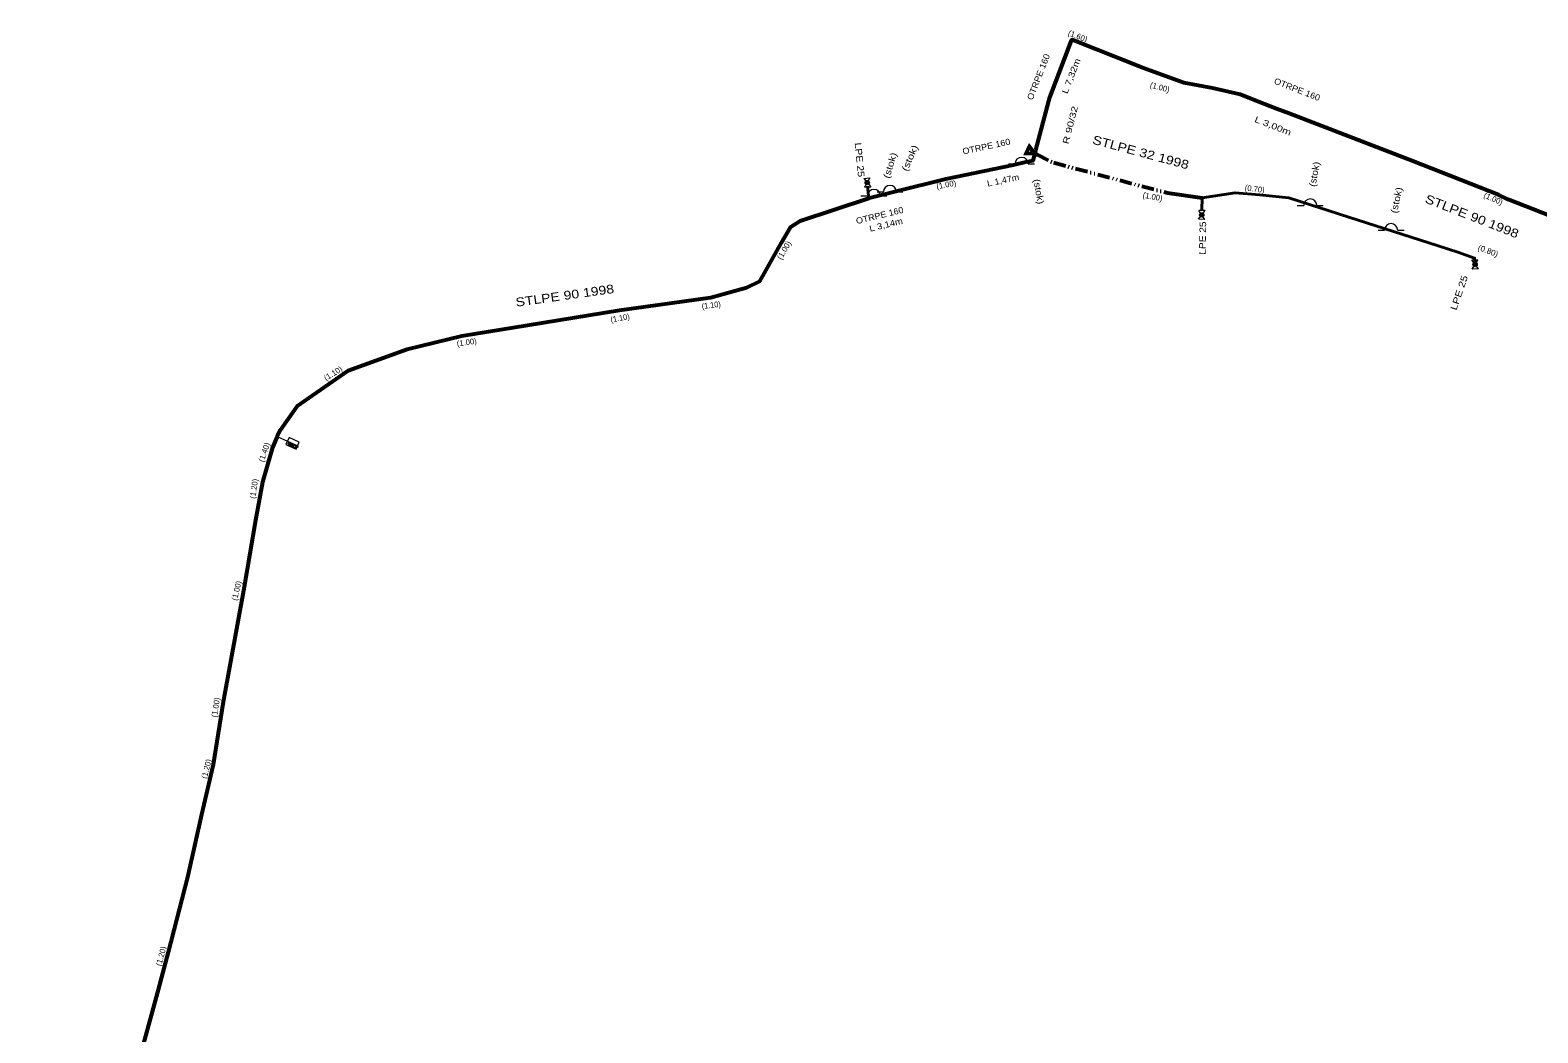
# Model space of a CAD drawing. Extents: x -648036 to -642998, y -1161549 to -1158141.
# Drawn here: x -647590.8 to -647418.7, y -1158574.2 to -1158459.8 of the extents above; entities that cross this region are included whole.
import ezdxf
from ezdxf.enums import TextEntityAlignment as Align

# ---------------------------------------------------------------- set-up
doc = ezdxf.new("R2010")
doc.units = 0
doc.header["$LTSCALE"] = 0.28
doc.header["$PDMODE"] = 32
doc.header["$PDSIZE"] = 0.14
doc.linetypes.add('DASH_DOUBLE_DOT', pattern=[9.2, 5, -1.2, 0.3, -1.2, 0.3, -1.2])
for name, color, linetype, lineweight in [('12', 7, 'DASH_DOUBLE_DOT', 40), ('14', 7, 'Continuous', 13), ('15', 7, 'Continuous', 13), ('19', 7, 'Continuous', 13), ('8', 7, 'Continuous', 53)]:
    doc.layers.add(name, color=color, linetype=linetype, lineweight=lineweight)
for name, color, linetype in [('20', 7, 'Continuous'), ('22', 7, 'Continuous'), ('24', 7, 'Continuous'), ('25', 7, 'Continuous'), ('27', 7, 'Continuous'), ('28', 7, 'Continuous')]:
    doc.layers.add(name, color=color, linetype=linetype)

msp = doc.modelspace()

# ---------------------------------------------------------------- linework, layer by layer
at = {"layer": '12'}
for p, q in [((-647495.08, -1158478.98), (-647495.26, -1158477.17)), ((-647457.02, -1158478.9), (-647457.07, -1158480.86))]:
    msp.add_line(p, q, dxfattribs=at)
at = {"layer": '12', "linetype": 'Continuous'}
msp.add_lwpolyline([(-647457.02, -1158478.9), (-647453.24, -1158478.35), (-647450.48, -1158478.58), (-647447.12, -1158478.92), (-647440.3, -1158481.12), (-647431.15, -1158484.03), (-647427.85, -1158485.1), (-647425.92, -1158485.78), (-647425.87, -1158486.52)], dxfattribs=at)
at = {"layer": '14'}
for p, q in [((-647447.11, -1158469.29), (-647449.91, -1158468.21)), ((-647478.58, -1158475.16), (-647477.14, -1158474.85)), ((-647495.02, -1158478.96), (-647491.96, -1158478.2))]:
    msp.add_line(p, q, dxfattribs=at)
msp.add_lwpolyline([(-647471.97, -1158460.95), (-647474.47, -1158467.45), (-647474.58, -1158467.86)], dxfattribs=at)
at = {"layer": '15'}
for p, q in [((-647479.115, -1158475.035), (-647478.38, -1158475.034)), ((-647476.894, -1158475.034), (-647476.16, -1158475.035)), ((-647495.664, -1158476.704), (-647494.956, -1158476.633)), ((-647495.664, -1158476.704), (-647494.856, -1158477.636)), ((-647494.956, -1158476.633), (-647495.564, -1158477.706)), ((-647495.975, -1158478.695), (-647495.24, -1158478.694)), ((-647495.564, -1158477.706), (-647494.856, -1158477.636)), ((-647494.145, -1158478.235), (-647493.41, -1158478.234)), ((-647493.754, -1158478.694), (-647493.02, -1158478.695)), ((-647491.924, -1158478.234), (-647491.19, -1158478.235)), ((-647457.439, -1158481.355), (-647456.701, -1158480.366)), ((-647456.701, -1158480.366), (-647457.413, -1158480.347)), ((-647456.727, -1158481.373), (-647457.413, -1158480.347)), ((-647446.165, -1158479.775), (-647445.43, -1158479.774)), ((-647443.944, -1158479.774), (-647443.21, -1158479.775)), ((-647456.727, -1158481.373), (-647457.439, -1158481.355)), ((-647436.935, -1158482.585), (-647436.2, -1158482.584)), ((-647434.714, -1158482.584), (-647433.98, -1158482.585)), ((-647425.549, -1158485.994), (-647426.259, -1158486.041)), ((-647425.481, -1158486.999), (-647426.259, -1158486.041)), ((-647426.191, -1158487.047), (-647425.549, -1158485.994)), ((-647425.481, -1158486.999), (-647426.191, -1158487.047)), ((-647562.604, -1158506.158), (-647560.267, -1158507.203)), ((-647560.648, -1158507.265), (-647561.229, -1158507.005)), ((-647560.324, -1158507.332), (-647560.267, -1158507.203))]:
    msp.add_line(p, q, dxfattribs=at)
for points in [[(-647477.391, -1158473.99), (-647475.85, -1158473.98), (-647476.788, -1158472.756), (-647477.09, -1158473.374)], [(-647477.23, -1158473.889), (-647476.052, -1158473.881), (-647476.769, -1158472.946)], [(-647477.069, -1158473.787), (-647476.253, -1158473.782), (-647476.75, -1158473.134)], [(-647476.908, -1158473.686), (-647476.455, -1158473.683), (-647476.731, -1158473.324)], [(-647561.259, -1158506.284), (-647561.614, -1158507.076), (-647560.445, -1158507.599), (-647560.091, -1158506.806)], [(-647561.325, -1158506.852), (-647561.412, -1158507.044), (-647560.537, -1158507.435), (-647560.451, -1158507.242)]]:
    msp.add_lwpolyline(points, close=True, dxfattribs=at)
for centre in [(-647477.6374, -1158475.0346), (-647492.6674, -1158478.2346), (-647494.4974, -1158478.6946), (-647444.6874, -1158479.7746), (-647435.4574, -1158482.5846)]:
    msp.add_arc(centre, 0.7431, 1.2748, 179.83951, dxfattribs=at)
msp.add_point((-647560.324, -1158507.332), dxfattribs=at)
at = {"layer": '19'}
for centre, radius in [((-647495.26, -1158477.17), 0.25), ((-647495.26, -1158477.17), 0.17), ((-647495.26, -1158477.17), 0.09), ((-647457.07, -1158480.86), 0.25), ((-647457.07, -1158480.86), 0.17), ((-647457.07, -1158480.86), 0.09), ((-647425.87, -1158486.52), 0.25), ((-647425.87, -1158486.52), 0.17), ((-647425.87, -1158486.52), 0.09)]:
    msp.add_circle(centre, radius, dxfattribs=at)
at = {"layer": '8', "linetype": 'DASH_DOUBLE_DOT'}
for p, q in [((-647476.04, -1158473.48), (-647476.14, -1158473.84)), ((-647476.14, -1158473.84), (-647475.85, -1158473.98))]:
    msp.add_line(p, q, dxfattribs=at)
at = {"layer": '8'}
msp.add_line((-647460.98, -1158478.35), (-647457.02, -1158478.9), dxfattribs=at)
for points in [[(-647402.25, -1158486.9), (-647408.77, -1158484.31), (-647413.05, -1158482.62), (-647413.74, -1158482.35), (-647415.38, -1158481.71), (-647422.11, -1158479.1), (-647423.18, -1158478.58), (-647432.96, -1158474.73), (-647447.11, -1158469.29), (-647448.52, -1158468.75), (-647449.91, -1158468.21), (-647452.68, -1158467.12), (-647455.85, -1158466.4), (-647459.12, -1158465.78), (-647463.73, -1158464.09), (-647471.86, -1158460.87), (-647471.97, -1158460.95), (-647474.47, -1158467.45), (-647474.58, -1158467.86), (-647476.04, -1158473.48)], [(-647476.14, -1158473.84), (-647476.36, -1158474.69), (-647477.14, -1158474.85), (-647478.58, -1158475.16), (-647486.28, -1158476.78), (-647491.96, -1158478.2), (-647495.02, -1158478.96), (-647495.08, -1158478.98)], [(-647495.08, -1158478.98), (-647502.9, -1158481.58), (-647504.06, -1158482.29), (-647505.08, -1158484.04), (-647507.57, -1158488.47), (-647509.06, -1158489.2), (-647513.14, -1158490.33)], [(-647513.14, -1158490.33), (-647523.54, -1158491.75), (-647534.05, -1158493.49), (-647541.54, -1158494.7), (-647547.77, -1158496.23), (-647554.52, -1158498.64), (-647560.39, -1158502.72), (-647562.27, -1158505.41), (-647562.604, -1158506.158)], [(-647562.604, -1158506.158), (-647563.16, -1158507.4), (-647564.31, -1158511.38), (-647565.09, -1158515.72), (-647566.37, -1158523.3), (-647568.79, -1158536.45), (-647569.92, -1158543.61), (-647571.25, -1158549.28), (-647572.87, -1158556.44), (-647575.06, -1158565.02), (-647576.21, -1158569.32), (-647577.99, -1158575.85), (-647579.5, -1158582.57), (-647581.46, -1158590.64), (-647584.27, -1158601.14), (-647586.03, -1158608.74), (-647588.21, -1158616.8), (-647590.82, -1158627.11)]]:
    msp.add_lwpolyline(points, dxfattribs=at)
at = {"layer": '8', "linetype": 'DASH_DOUBLE_DOT'}
msp.add_lwpolyline([(-647475.85, -1158473.98), (-647473.99, -1158474.89), (-647460.98, -1158478.35)], dxfattribs=at)

# ---------------------------------------------------------------- texts
at = {"layer": '20', "width": 1.2}
for s, rotation, p in [('STLPE 32 1998', 344.921, (-647464.1636, -1158474.1898)), ('STLPE 90 1998', 338.618, (-647426.4013, -1158481.4809)), ('STLPE 90 1998', 8.021, (-647529.7148, -1158490.5497))]:
    msp.add_text(s, height=1, rotation=rotation, dxfattribs=at).set_placement(p, align=Align.CENTER)
at = {"layer": '22'}
for rotation, width, p in [(275.593, 1.2, (-647496.4982, -1158474.603)), (88.808, 1.15, (-647456.6029, -1158483.5073)), (71.047, 1.25, (-647427.3392, -1158489.8563))]:
    msp.add_text('LPE 25', height=0.75, rotation=rotation, dxfattribs=dict(at, width=width)).set_placement(p, align=Align.CENTER)
at = {"layer": '24'}
for s, rotation, width, p in [('OTRPE 160', 68.755, 1.1, (-647475.3864, -1158465.2318)), ('L 7,32m', 68.755, 1.25, (-647471.6548, -1158465.1288)), ('OTRPE 160', 338.618, 1.1, (-647446.3111, -1158466.8542)), ('L 3,00m', 338.618, 1.3, (-647449.0686, -1158471.0184)), ('OTRPE 160', 12.032, 1.1, (-647481.585, -1158473.3826)), ('L 1,47m', 12.032, 1.1, (-647479.6785, -1158477.244)), ('OTRPE 160', 13.751, 1.1, (-647493.7532, -1158481.2527)), ('L 3,14m', 13.751, 1.15, (-647493.0357, -1158482.3158))]:
    msp.add_text(s, height=0.7, rotation=rotation, dxfattribs=dict(at, width=width)).set_placement(p, align=Align.CENTER)
at = {"layer": '25', "width": 1.35}
msp.add_text('R 90/32', height=0.7, rotation=75.63, dxfattribs=at).set_placement((-647471.7436, -1158470.6849), align=Align.CENTER)
at = {"layer": '27'}
for s, rotation, p in [('(1.60)', 338.045, (-647471.35, -1158460.7484)), ('(1.00)', 344.921, (-647461.9366, -1158466.5989)), ('(1.00)', 10.886, (-647486.1819, -1158477.7195)), ('(0.70)', 352.942, (-647451.0639, -1158478.2097)), ('(1.00)', 349.504, (-647462.7347, -1158479.0902)), ('(1.00)', 336.326, (-647423.922, -1158479.3001)), ('(1.00)', 59.588, (-647504.4778, -1158485.0495)), ('(1.00)', 8.021, (-647540.9389, -1158495.7169)), ('(1.10)', 31.513, (-647556.0654, -1158499.2219)), ('(1.40)', 71.047, (-647563.7926, -1158508.0461)), ('(1.20)', 82.506, (-647564.9496, -1158512.1524)), ('(1.00)', 76.776, (-647566.9404, -1158523.8278)), ('(1.00)', 80.787, (-647569.3179, -1158537.1315)), ('(1.20)', 75.63, (-647570.3785, -1158544.1702)), ('(1.20)', 74.485, (-647575.558, -1158565.5524))]:
    msp.add_text(s, height=0.65, rotation=rotation, dxfattribs=at).set_placement(p, align=Align.CENTER)
for s, rotation, width, p in [('(0.80)', 339.191, 1.05, (-647424.4985, -1158485.2507)), ('(1.10)', 6.875, 0.8, (-647513.0309, -1158491.4742)), ('(1.10)', 10.313, 0.85, (-647523.4192, -1158492.9427))]:
    msp.add_text(s, height=0.65, rotation=rotation, dxfattribs=dict(at, width=width)).set_placement(p, align=Align.CENTER)
at = {"layer": '28'}
for rotation, width, p in [(72.766, 1.2, (-647492.2938, -1158475.3146)), (65.89, 1.25, (-647490.0542, -1158474.5182)), (79.641, 1.15, (-647443.8417, -1158476.2739)), (280.176, 1.15, (-647476.0435, -1158478.2552)), (77.922, 1.2, (-647434.4734, -1158479.2545))]:
    msp.add_text('(stok)', height=0.75, rotation=rotation, dxfattribs=dict(at, width=width)).set_placement(p, align=Align.CENTER)

doc.saveas('drawing.dxf')
